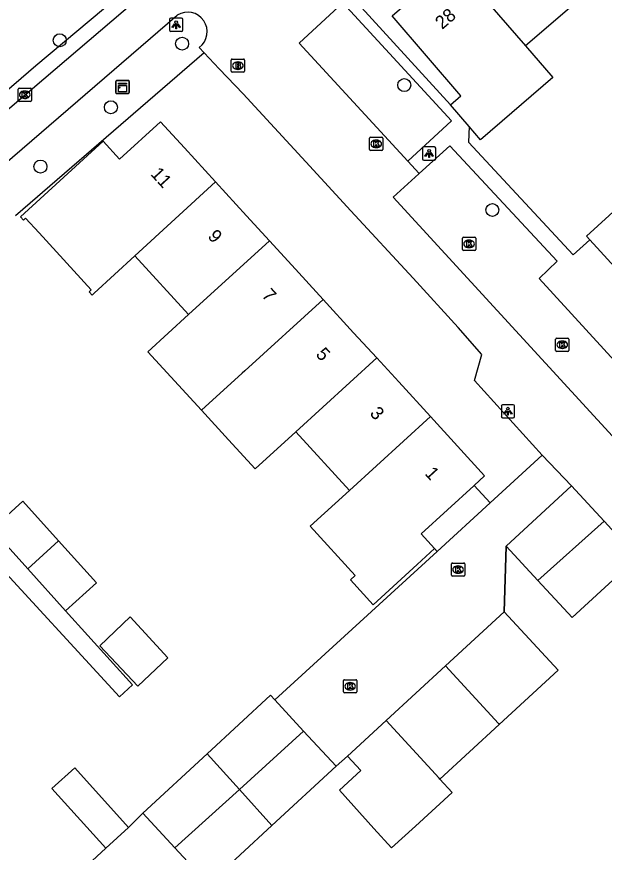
# Model space of a CAD drawing. Extents: x 158474 to 159560, y 388525 to 389605.
# Drawn here: x 159037.6 to 159082, y 388903.3 to 388966.4 of the extents above; entities that cross this region are included whole.
import ezdxf

# ---------------------------------------------------------------- set-up
doc = ezdxf.new("R2010")
doc.units = 0
for name, color, linetype in [('IMGEO_Boom', 7, 'Continuous'), ('IMGEO_Brandkraan', 7, 'Continuous'), ('IMGEO_Fietspad_gesloten', 7, 'Continuous'), ('IMGEO_Groenvoorziening', 7, 'Continuous'), ('IMGEO_Hek', 7, 'Continuous'), ('IMGEO_Kast', 7, 'Continuous'), ('IMGEO_Kolk', 7, 'Continuous'), ('IMGEO_Lichtpunt', 7, 'Continuous'), ('IMGEO_Muur', 7, 'Continuous'), ('IMGEO_Pand', 7, 'Continuous'), ('IMGEO_Pand_nummerreeks', 7, 'Continuous'), ('IMGEO_Rijbaan_lokaal_open', 7, 'Continuous'), ('IMGEO_Voetpad_open', 7, 'Continuous')]:
    doc.layers.add(name, color=color, linetype=linetype)

msp = doc.modelspace()

# ---------------------------------------------------------------- linework, layer by layer
at = {"layer": 'IMGEO_Boom'}
for centre in [(159040.871, 388964.606), (159050.107, 388964.349), (159066.882, 388961.222), (159044.73, 388959.546), (159039.41, 388955.073), (159073.534, 388951.792)]:
    msp.add_circle(centre, 0.489, dxfattribs=at)
at = {"layer": 'IMGEO_Brandkraan'}
for p, q in [((159053.896, 388963.19), (159054.748, 388963.19)), ((159053.821, 388962.264), (159053.821, 388963.116)), ((159054.309, 388962.97), (159054.334, 388962.97)), ((159054.822, 388963.116), (159054.822, 388962.264)), ((159054.748, 388962.19), (159053.896, 388962.19)), ((159054.332, 388962.41), (159054.307, 388962.41))]:
    msp.add_line(p, q, dxfattribs=at)
for points in [[(159053.896, 388963.19), (159054.748, 388963.19)], [(159053.821, 388962.264), (159053.821, 388963.116)], [(159054.169, 388962.89), (159054.169, 388962.49), (159054.382, 388962.49)], [(159054.4, 388962.89), (159054.169, 388962.89)], [(159054.348, 388962.809), (159054.294, 388962.809), (159054.294, 388962.733)], [(159054.294, 388962.733), (159054.347, 388962.733)], [(159054.356, 388962.657), (159054.294, 388962.657), (159054.294, 388962.576)], [(159054.294, 388962.576), (159054.356, 388962.576)], [(159054.822, 388963.116), (159054.822, 388962.264)], [(159054.748, 388962.19), (159053.896, 388962.19)]]:
    msp.add_lwpolyline(points, dxfattribs=at)
for centre, radius, start, end in [((159053.898, 388963.114), 0.0765, 91.55205, 178.44795), ((159053.898, 388963.114), 0.0765, 91.55205, 178.44795), ((159054.746, 388963.114), 0.0765, 1.55205, 88.44795), ((159054.746, 388963.114), 0.0765, 1.55205, 88.44795), ((159054.349, 388962.771), 0.0379, 267.82845, 90.93552), ((159054.357, 388962.616), 0.0404, 269.87594, 90.50774), ((159054.404, 388962.745), 0.145, 59.4692, 91.53667), ((159054.429, 388962.792), 0.0922, 285.51372, 58.15012), ((159054.434, 388962.6), 0.105, 301.31148, 78.98903), ((159053.898, 388962.266), 0.0765, 181.55205, 268.44795), ((159053.898, 388962.266), 0.0765, 181.55205, 268.44795), ((159054.388, 388962.741), 0.251, 268.66757, 293.53466), ((159054.746, 388962.266), 0.0765, 271.55205, 358.44795), ((159054.746, 388962.266), 0.0765, 271.55205, 358.44795)]:
    msp.add_arc(centre, radius, start, end, dxfattribs=at)
for centre, major_axis, ratio, start_param, end_param in [((159054.308, 388962.69), (-0.387, 0.002), 0.722429, 4.712389, 7.853982), ((159054.333, 388962.69), (-0.39, 0.002), 0.717154, 1.570796, 4.712389)]:
    msp.add_ellipse(centre, major_axis=major_axis, ratio=ratio, start_param=start_param, end_param=end_param, dxfattribs=at)
at = {"layer": 'IMGEO_Fietspad_gesloten'}
for points in [[(158982.556, 388907.1), (158984.126, 388908.89), (158991.035, 388916.747), (158993.803, 388919.761), (158997.258, 388923.376), (159000, 388926.236), (159000.439, 388926.694), (159004.156, 388930.365), (159007.355, 388933.494), (159010.208, 388936.145), (159013.072, 388938.778), (159015.935, 388941.39), (159018.694, 388943.743), (159033.647, 388956.597), (159049.939, 388970.49), (159054.573, 388974.475), (159070.579, 388988.241), (159084.209, 389000), (159114.372, 389026.022)], [(159035.257, 388954.041), (159049.743, 388966.513)]]:
    msp.add_lwpolyline(points, dxfattribs=at)
at = {"layer": 'IMGEO_Groenvoorziening'}
msp.add_lwpolyline([(159051.772, 388963.65), (159037.514, 388951.357)], dxfattribs=at)
at = {"layer": 'IMGEO_Hek'}
msp.add_lwpolyline([(159074.429, 388921.462), (159074.582, 388926.417)], dxfattribs=at)
at = {"layer": 'IMGEO_Kast'}
for p, q in [((159045.107, 388960.651), (159045.107, 388961.492)), ((159045.107, 388961.492), (159045.107, 388960.651)), ((159045.182, 388961.576), (159046.023, 388961.576)), ((159046.023, 388961.576), (159045.182, 388961.576)), ((159046.107, 388961.501), (159046.107, 388960.66)), ((159046.107, 388960.66), (159046.107, 388961.501)), ((159046.032, 388960.576), (159045.191, 388960.576)), ((159045.191, 388960.576), (159046.032, 388960.576))]:
    msp.add_line(p, q, dxfattribs=at)
for points in [[(159045.302, 388961.366), (159045.902, 388961.366), (159045.902, 388961.281), (159045.302, 388961.281), (159045.302, 388961.366)], [(159045.302, 388961.191), (159045.902, 388961.191), (159045.902, 388960.702), (159045.302, 388960.702), (159045.302, 388961.191)]]:
    msp.add_lwpolyline(points, dxfattribs=at)
msp.add_circle((159045.386, 388961.04), 0.0377, dxfattribs=at)
for centre, start, end in [((159045.185, 388961.498), 92.4484, 184.28452), ((159045.185, 388961.498), 92.4484, 184.28452), ((159046.029, 388961.498), 2.4484, 94.28452), ((159046.029, 388961.498), 2.4484, 94.28452), ((159045.185, 388960.654), 182.4484, 274.28452), ((159045.185, 388960.654), 182.4484, 274.28452), ((159046.029, 388960.654), 272.4484, 4.28452), ((159046.029, 388960.654), 272.4484, 4.28452)]:
    msp.add_arc(centre, 0.0779, start, end, dxfattribs=at)
at = {"layer": 'IMGEO_Kolk'}
for p, q in [((159037.721, 388960.066), (159037.721, 388960.918)), ((159037.796, 388960.992), (159038.648, 388960.992)), ((159038.209, 388960.772), (159038.234, 388960.772)), ((159038.722, 388960.918), (159038.722, 388960.066)), ((159038.232, 388960.212), (159038.207, 388960.212)), ((159038.648, 388959.992), (159037.796, 388959.992)), ((159064.263, 388956.358), (159064.263, 388957.21)), ((159064.338, 388957.284), (159065.19, 388957.284)), ((159064.751, 388957.064), (159064.776, 388957.064)), ((159065.264, 388957.21), (159065.264, 388956.358)), ((159065.19, 388956.284), (159064.338, 388956.284)), ((159064.774, 388956.504), (159064.749, 388956.504)), ((159071.276, 388948.807), (159071.276, 388949.659)), ((159071.351, 388949.733), (159072.203, 388949.733)), ((159071.764, 388949.513), (159071.789, 388949.513)), ((159072.277, 388949.659), (159072.277, 388948.807)), ((159072.203, 388948.733), (159071.351, 388948.733)), ((159071.787, 388948.953), (159071.762, 388948.953)), ((159078.314, 388941.192), (159078.314, 388942.044)), ((159078.389, 388942.118), (159079.241, 388942.118)), ((159078.802, 388941.898), (159078.827, 388941.898)), ((159079.315, 388942.044), (159079.315, 388941.192)), ((159079.241, 388941.118), (159078.389, 388941.118)), ((159078.825, 388941.338), (159078.8, 388941.338)), ((159070.447, 388924.213), (159070.447, 388925.065)), ((159070.522, 388925.139), (159071.374, 388925.139)), ((159070.935, 388924.919), (159070.96, 388924.919)), ((159071.448, 388925.065), (159071.448, 388924.213)), ((159071.374, 388924.139), (159070.522, 388924.139)), ((159070.958, 388924.359), (159070.933, 388924.359)), ((159062.295, 388915.404), (159062.295, 388916.256)), ((159062.37, 388916.33), (159063.222, 388916.33)), ((159062.783, 388916.11), (159062.808, 388916.11)), ((159063.296, 388916.256), (159063.296, 388915.404)), ((159063.222, 388915.33), (159062.37, 388915.33)), ((159062.806, 388915.55), (159062.781, 388915.55))]:
    msp.add_line(p, q, dxfattribs=at)
for points in [[(159037.721, 388960.066), (159037.721, 388960.918)], [(159037.796, 388960.992), (159038.648, 388960.992)], [(159038.042, 388960.692), (159038.165, 388960.692), (159038.165, 388960.541), (159038.295, 388960.692), (159038.459, 388960.692), (159038.313, 388960.541), (159038.466, 388960.292), (159038.314, 388960.292), (159038.229, 388960.456), (159038.165, 388960.389), (159038.165, 388960.292), (159038.042, 388960.292), (159038.042, 388960.692)], [(159038.722, 388960.918), (159038.722, 388960.066)], [(159038.648, 388959.992), (159037.796, 388959.992)], [(159064.263, 388956.358), (159064.263, 388957.21)], [(159064.338, 388957.284), (159065.19, 388957.284)], [(159064.584, 388956.984), (159064.707, 388956.984), (159064.707, 388956.833), (159064.837, 388956.984), (159065.001, 388956.984), (159064.855, 388956.833), (159065.008, 388956.584), (159064.856, 388956.584), (159064.771, 388956.748), (159064.707, 388956.681), (159064.707, 388956.584), (159064.584, 388956.584), (159064.584, 388956.984)], [(159065.264, 388957.21), (159065.264, 388956.358)], [(159065.19, 388956.284), (159064.338, 388956.284)], [(159071.276, 388948.807), (159071.276, 388949.659)], [(159071.351, 388949.733), (159072.203, 388949.733)], [(159071.597, 388949.433), (159071.72, 388949.433), (159071.72, 388949.282), (159071.85, 388949.433), (159072.014, 388949.433), (159071.868, 388949.282), (159072.021, 388949.033), (159071.869, 388949.033), (159071.784, 388949.197), (159071.72, 388949.13), (159071.72, 388949.033), (159071.597, 388949.033), (159071.597, 388949.433)], [(159072.277, 388949.659), (159072.277, 388948.807)], [(159072.203, 388948.733), (159071.351, 388948.733)], [(159078.314, 388941.192), (159078.314, 388942.044)], [(159078.389, 388942.118), (159079.241, 388942.118)], [(159078.635, 388941.818), (159078.758, 388941.818), (159078.758, 388941.667), (159078.888, 388941.818), (159079.052, 388941.818), (159078.906, 388941.667), (159079.059, 388941.418), (159078.907, 388941.418), (159078.822, 388941.582), (159078.758, 388941.515), (159078.758, 388941.418), (159078.635, 388941.418), (159078.635, 388941.818)], [(159079.315, 388942.044), (159079.315, 388941.192)], [(159079.241, 388941.118), (159078.389, 388941.118)], [(159070.447, 388924.213), (159070.447, 388925.065)], [(159070.522, 388925.139), (159071.374, 388925.139)], [(159070.768, 388924.839), (159070.891, 388924.839), (159070.891, 388924.688), (159071.021, 388924.839), (159071.185, 388924.839), (159071.039, 388924.688), (159071.192, 388924.439), (159071.04, 388924.439), (159070.955, 388924.603), (159070.891, 388924.536), (159070.891, 388924.439), (159070.768, 388924.439), (159070.768, 388924.839)], [(159071.448, 388925.065), (159071.448, 388924.213)], [(159071.374, 388924.139), (159070.522, 388924.139)], [(159062.295, 388915.404), (159062.295, 388916.256)], [(159062.37, 388916.33), (159063.222, 388916.33)], [(159062.616, 388916.03), (159062.739, 388916.03), (159062.739, 388915.879), (159062.869, 388916.03), (159063.033, 388916.03), (159062.887, 388915.879), (159063.04, 388915.63), (159062.888, 388915.63), (159062.803, 388915.794), (159062.739, 388915.727), (159062.739, 388915.63), (159062.616, 388915.63), (159062.616, 388916.03)], [(159063.296, 388916.256), (159063.296, 388915.404)], [(159063.222, 388915.33), (159062.37, 388915.33)]]:
    msp.add_lwpolyline(points, dxfattribs=at)
for centre, start, end in [((159037.798, 388960.916), 91.55205, 178.44795), ((159037.798, 388960.916), 91.55205, 178.44795), ((159038.646, 388960.916), 1.55205, 88.44795), ((159038.646, 388960.916), 1.55205, 88.44795), ((159037.798, 388960.068), 181.55205, 268.44795), ((159037.798, 388960.068), 181.55205, 268.44795), ((159038.646, 388960.068), 271.55205, 358.44795), ((159038.646, 388960.068), 271.55205, 358.44795), ((159064.34, 388957.208), 91.55205, 178.44795), ((159064.34, 388957.208), 91.55205, 178.44795), ((159065.188, 388957.208), 1.55205, 88.44795), ((159065.188, 388957.208), 1.55205, 88.44795), ((159064.34, 388956.36), 181.55205, 268.44795), ((159064.34, 388956.36), 181.55205, 268.44795), ((159065.188, 388956.36), 271.55205, 358.44795), ((159065.188, 388956.36), 271.55205, 358.44795), ((159071.353, 388949.657), 91.55205, 178.44795), ((159071.353, 388949.657), 91.55205, 178.44795), ((159072.201, 388949.657), 1.55205, 88.44795), ((159072.201, 388949.657), 1.55205, 88.44795), ((159071.353, 388948.809), 181.55205, 268.44795), ((159071.353, 388948.809), 181.55205, 268.44795), ((159072.201, 388948.809), 271.55205, 358.44795), ((159072.201, 388948.809), 271.55205, 358.44795), ((159078.391, 388942.042), 91.55205, 178.44795), ((159078.391, 388942.042), 91.55205, 178.44795), ((159079.239, 388942.042), 1.55205, 88.44795), ((159079.239, 388942.042), 1.55205, 88.44795), ((159078.391, 388941.194), 181.55205, 268.44795), ((159078.391, 388941.194), 181.55205, 268.44795), ((159079.239, 388941.194), 271.55205, 358.44795), ((159079.239, 388941.194), 271.55205, 358.44795), ((159070.524, 388925.063), 91.55205, 178.44795), ((159070.524, 388925.063), 91.55205, 178.44795), ((159071.372, 388925.063), 1.55205, 88.44795), ((159071.372, 388925.063), 1.55205, 88.44795), ((159070.524, 388924.215), 181.55205, 268.44795), ((159070.524, 388924.215), 181.55205, 268.44795), ((159071.372, 388924.215), 271.55205, 358.44795), ((159071.372, 388924.215), 271.55205, 358.44795), ((159062.372, 388916.254), 91.55205, 178.44795), ((159062.372, 388916.254), 91.55205, 178.44795), ((159063.22, 388916.254), 1.55205, 88.44795), ((159063.22, 388916.254), 1.55205, 88.44795), ((159062.372, 388915.406), 181.55205, 268.44795), ((159062.372, 388915.406), 181.55205, 268.44795), ((159063.22, 388915.406), 271.55205, 358.44795), ((159063.22, 388915.406), 271.55205, 358.44795)]:
    msp.add_arc(centre, 0.0765, start, end, dxfattribs=at)
for centre, major_axis, ratio, start_param, end_param in [((159038.208, 388960.492), (-0.387, 0.002), 0.722429, 4.712389, 7.853982), ((159038.233, 388960.492), (-0.39, 0.002), 0.717154, 1.570796, 4.712389), ((159064.75, 388956.784), (-0.387, 0.002), 0.722429, 4.712389, 7.853982), ((159064.775, 388956.784), (-0.39, 0.002), 0.717154, 1.570796, 4.712389), ((159071.763, 388949.233), (-0.387, 0.002), 0.722429, 4.712389, 7.853982), ((159071.788, 388949.233), (-0.39, 0.002), 0.717154, 1.570796, 4.712389), ((159078.801, 388941.618), (-0.387, 0.002), 0.722429, 4.712389, 7.853982), ((159078.826, 388941.618), (-0.39, 0.002), 0.717154, 1.570796, 4.712389), ((159070.934, 388924.639), (-0.387, 0.002), 0.722429, 4.712389, 7.853982), ((159070.959, 388924.639), (-0.39, 0.002), 0.717154, 1.570796, 4.712389), ((159062.782, 388915.83), (-0.387, 0.002), 0.722429, 4.712389, 7.853982), ((159062.807, 388915.83), (-0.39, 0.002), 0.717154, 1.570796, 4.712389)]:
    msp.add_ellipse(centre, major_axis=major_axis, ratio=ratio, start_param=start_param, end_param=end_param, dxfattribs=at)
at = {"layer": 'IMGEO_Lichtpunt'}
for p, q in [((159049.16, 388966.182), (159049.16, 388965.375)), ((159049.16, 388966.182), (159049.16, 388965.375)), ((159050.062, 388966.277), (159049.254, 388966.277)), ((159050.062, 388966.277), (159049.254, 388966.277)), ((159050.156, 388965.375), (159050.156, 388966.182)), ((159050.156, 388965.375), (159050.156, 388966.182)), ((159049.254, 388965.281), (159050.062, 388965.281)), ((159049.254, 388965.281), (159050.062, 388965.281)), ((159068.258, 388956.458), (159068.258, 388955.651)), ((159068.258, 388956.458), (159068.258, 388955.651)), ((159069.16, 388956.553), (159068.352, 388956.553)), ((159069.16, 388956.553), (159068.352, 388956.553)), ((159069.254, 388955.651), (159069.254, 388956.458)), ((159069.254, 388955.651), (159069.254, 388956.458)), ((159068.352, 388955.557), (159069.16, 388955.557)), ((159068.352, 388955.557), (159069.16, 388955.557)), ((159074.212, 388936.998), (159074.212, 388936.191)), ((159074.212, 388936.998), (159074.212, 388936.191)), ((159075.114, 388937.093), (159074.306, 388937.093)), ((159075.114, 388937.093), (159074.306, 388937.093)), ((159075.208, 388936.191), (159075.208, 388936.998)), ((159075.208, 388936.191), (159075.208, 388936.998)), ((159074.306, 388936.097), (159075.114, 388936.097)), ((159074.306, 388936.097), (159075.114, 388936.097))]:
    msp.add_line(p, q, dxfattribs=at)
for points in [[(159049.534, 388965.846), (159049.573, 388965.818), (159049.385, 388965.556), (159049.347, 388965.583), (159049.534, 388965.846)], [(159049.636, 388965.798), (159049.683, 388965.798), (159049.683, 388965.476), (159049.636, 388965.476), (159049.636, 388965.798)], [(159049.746, 388965.818), (159049.784, 388965.845), (159049.971, 388965.583), (159049.932, 388965.555), (159049.746, 388965.818)], [(159068.632, 388956.122), (159068.671, 388956.094), (159068.483, 388955.832), (159068.445, 388955.859), (159068.632, 388956.122)], [(159068.734, 388956.074), (159068.781, 388956.074), (159068.781, 388955.752), (159068.734, 388955.752), (159068.734, 388956.074)], [(159068.844, 388956.094), (159068.882, 388956.121), (159069.069, 388955.859), (159069.03, 388955.831), (159068.844, 388956.094)], [(159074.586, 388936.662), (159074.625, 388936.634), (159074.437, 388936.372), (159074.399, 388936.399), (159074.586, 388936.662)], [(159074.798, 388936.634), (159074.836, 388936.661), (159075.023, 388936.399), (159074.984, 388936.371), (159074.798, 388936.634)], [(159074.688, 388936.614), (159074.735, 388936.614), (159074.735, 388936.292), (159074.688, 388936.292), (159074.688, 388936.614)]]:
    msp.add_lwpolyline(points, dxfattribs=at)
for centre in [(159049.659, 388965.98), (159068.757, 388956.256), (159074.711, 388936.796)]:
    msp.add_circle(centre, 0.0994, dxfattribs=at)
for centre, start, end in [((159049.254, 388966.182), 90, 180), ((159049.254, 388966.182), 90, 180), ((159050.062, 388966.182), 0, 90), ((159050.062, 388966.182), 0, 90), ((159049.254, 388965.375), 180, 270), ((159049.254, 388965.375), 180, 270), ((159050.062, 388965.375), 270, 0), ((159050.062, 388965.375), 270, 360), ((159068.352, 388956.458), 90, 180), ((159068.352, 388956.458), 90, 180), ((159069.16, 388956.458), 0, 90), ((159069.16, 388956.458), 0, 90), ((159068.352, 388955.651), 180, 270), ((159068.352, 388955.651), 180, 270), ((159069.16, 388955.651), 270, 0), ((159069.16, 388955.651), 270, 360), ((159074.306, 388936.998), 90, 180), ((159074.306, 388936.998), 90, 180), ((159075.114, 388936.998), 0, 90), ((159075.114, 388936.998), 0, 90), ((159074.306, 388936.191), 180, 270), ((159074.306, 388936.191), 180, 270), ((159075.114, 388936.191), 270, 0), ((159075.114, 388936.191), 270, 360)]:
    msp.add_arc(centre, 0.0946, start, end, dxfattribs=at)
at = {"layer": 'IMGEO_Muur'}
msp.add_lwpolyline([(159071.795, 388958.09), (159071.74, 388956.903), (159079.631, 388948.405)], dxfattribs=at)
at = {"layer": 'IMGEO_Pand'}
for points in [[(159070.383, 388959.731), (159071.162, 388960.402), (159065.957, 388966.45), (159070.61, 388970.456)], [(159070.61, 388970.456), (159076.04, 388964.187)], [(159079.662, 388969.176), (159080.585, 388968.1), (159076.04, 388964.187)], [(159076.04, 388964.187), (159078.1, 388961.795), (159072.647, 388957.1), (159071.795, 388958.09)], [(159071.795, 388958.09), (159070.383, 388959.731)], [(159046.534, 388948.322), (159043.474, 388945.52), (159043.304, 388945.365), (159043.081, 388945.609), (159043.251, 388945.764), (159039.312, 388950.065), (159038.292, 388951.179), (159038.123, 388951.023), (159037.9, 388951.267), (159044.149, 388956.989), (159045.391, 388955.632), (159048.474, 388958.455), (159050.28, 388956.482), (159052.637, 388953.909)], [(159052.637, 388953.909), (159046.534, 388948.322)], [(159052.637, 388953.909), (159054.98, 388951.351), (159056.697, 388949.475)], [(159080.886, 388949.549), (159080.65, 388949.807), (159085.506, 388954.236), (159087.885, 388951.628)], [(159056.697, 388949.475), (159050.592, 388943.89)], [(159056.697, 388949.475), (159058.38, 388947.638), (159060.754, 388945.045)], [(159083.034, 388947.194), (159080.886, 388949.549)], [(159050.592, 388943.89), (159046.534, 388948.322)], [(159060.754, 388945.045), (159054.841, 388939.653), (159054.641, 388939.47), (159051.575, 388936.674)], [(159060.754, 388945.045), (159063.058, 388942.529), (159064.805, 388940.621)], [(159051.575, 388936.674), (159047.531, 388941.09), (159050.592, 388943.89)], [(159058.689, 388935.049), (159064.805, 388940.621)], [(159064.805, 388940.621), (159066.462, 388938.812), (159068.864, 388936.188)], [(159058.689, 388935.049), (159055.629, 388932.247), (159053.618, 388934.443), (159051.575, 388936.674)], [(159068.864, 388936.188), (159062.747, 388930.618)], [(159068.864, 388936.188), (159072.95, 388931.727), (159072.153, 388930.997)], [(159062.747, 388930.618), (159058.689, 388935.049)], [(159072.153, 388930.997), (159072.125, 388930.971), (159068.149, 388927.33), (159069.163, 388926.223)], [(159072.153, 388930.997), (159073.36, 388929.677)], [(159069.163, 388926.223), (159067.862, 388925.032), (159064.543, 388921.993), (159062.821, 388923.873), (159063.187, 388924.192), (159059.789, 388927.924), (159062.747, 388930.618)], [(159074.582, 388926.417), (159079.511, 388930.955)], [(159079.511, 388930.955), (159081.967, 388928.286)], [(159040.774, 388926.824), (159038.082, 388929.805), (159035.749, 388927.698)], [(159069.354, 388926.014), (159073.36, 388929.677)], [(159076.965, 388923.829), (159081.967, 388928.286)], [(159081.967, 388928.286), (159084.485, 388925.551)], [(159038.451, 388924.705), (159035.749, 388927.698)], [(159040.774, 388926.824), (159038.451, 388924.705)], [(159041.308, 388921.54), (159043.642, 388923.647), (159040.774, 388926.824)], [(159069.354, 388926.014), (159069.163, 388926.223)], [(159076.965, 388923.829), (159074.582, 388926.417)], [(159084.485, 388925.551), (159079.556, 388921.014), (159076.965, 388923.829)], [(159041.308, 388921.54), (159038.451, 388924.705)], [(159046.184, 388921.073), (159043.883, 388918.896), (159046.772, 388915.844), (159049.023, 388917.976), (159046.184, 388921.073)], [(159069.992, 388917.372), (159074.429, 388921.462)], [(159074.429, 388921.462), (159078.495, 388917.051), (159074.044, 388912.948)], [(159065.512, 388913.243), (159069.992, 388917.372)], [(159069.992, 388917.372), (159073.99, 388913.02), (159074.044, 388912.948)], [(159051.996, 388910.732), (159056.776, 388915.153), (159057.097, 388914.806)], [(159057.097, 388914.806), (159059.274, 388912.453)], [(159065.512, 388913.243), (159062.593, 388910.552)], [(159069.568, 388908.823), (159069.51, 388908.9), (159065.512, 388913.243)], [(159074.044, 388912.948), (159069.568, 388908.823)], [(159054.43, 388908.05), (159059.274, 388912.453)], [(159059.274, 388912.453), (159061.734, 388909.793)], [(159047.144, 388906.244), (159051.996, 388910.732)], [(159051.996, 388910.732), (159054.43, 388908.05)], [(159062.593, 388910.552), (159063.59, 388909.47), (159061.985, 388907.991), (159064.591, 388905.105), (159065.927, 388903.625), (159067.728, 388905.28), (159070.489, 388907.822), (159069.568, 388908.823)], [(159044.34, 388903.612), (159040.28, 388908.103), (159042.012, 388909.668), (159046.071, 388905.177)], [(159061.734, 388909.793), (159056.892, 388905.314)], [(159049.561, 388903.63), (159054.43, 388908.05)], [(159054.43, 388908.05), (159056.88, 388905.33), (159056.892, 388905.314)], [(159047.144, 388906.244), (159049.561, 388903.63)], [(159044.34, 388903.612), (159046.071, 388905.177)], [(159056.892, 388905.314), (159052.102, 388900.883)], [(159049.561, 388903.63), (159052.102, 388900.883)]]:
    msp.add_lwpolyline(points, dxfattribs=at)
at = {"layer": 'IMGEO_Rijbaan_lokaal_open'}
for points in [[(159068.016, 388954.544), (159070.323, 388956.636), (159078.421, 388947.93), (159077.068, 388946.614), (159092.522, 388929.727)], [(159089.944, 388926.697), (159083.426, 388933.811), (159066.034, 388952.748), (159067.989, 388954.52), (159068.016, 388954.544)], [(159073.36, 388929.677), (159077.292, 388933.272)], [(159077.292, 388933.272), (159079.511, 388930.955)], [(159057.097, 388914.806), (159069.354, 388926.014)], [(159074.582, 388926.417), (159074.429, 388921.462)], [(159062.593, 388910.552), (159061.734, 388909.793)], [(159046.071, 388905.177), (159047.144, 388906.244)], [(159038.924, 388898.606), (159044.34, 388903.612)]]:
    msp.add_lwpolyline(points, dxfattribs=at)
at = {"layer": 'IMGEO_Voetpad_open'}
for points in [[(159053.465, 388974.766), (159039.062, 388962.688), (159030.194, 388955.059)], [(159070.383, 388959.731), (159062.836, 388967.979)], [(159067.162, 388955.486), (159058.942, 388964.389), (159062.236, 388967.43)], [(159062.236, 388967.43), (159070.455, 388958.526), (159067.162, 388955.486)], [(159051.407, 388964.07), (159051.772, 388963.65)], [(159077.292, 388933.272), (159072.177, 388938.914), (159072.727, 388940.876), (159070.954, 388942.926), (159067.55, 388946.643), (159062.838, 388951.72), (159059.438, 388955.433), (159054.726, 388960.554), (159052.916, 388962.443), (159051.772, 388963.65)], [(159071.795, 388958.09), (159071.74, 388956.903), (159079.631, 388948.405), (159080.886, 388949.549)], [(159067.162, 388955.486), (159068.016, 388954.544)], [(159035.368, 388925.912), (159045.37, 388915.032), (159046.359, 388915.941), (159041.308, 388921.54)]]:
    msp.add_lwpolyline(points, dxfattribs=at)
msp.add_arc((159050.516, 388965.251), 1.48, 307.02918, 121.4907, dxfattribs=at)

# ---------------------------------------------------------------- texts
at = {"layer": 'IMGEO_Pand_nummerreeks'}
for s, rotation, p in [('28', 40.72196, (159069.746, 388965.384)), ('11', 312.4817, (159047.675, 388954.471)), ('9', 312.4817, (159051.988, 388949.761)), ('7', 312.47888, (159056.068, 388945.306)), ('5', 312.47888, (159060.147, 388940.851)), ('3', 312.4817, (159064.226, 388936.397)), ('1', 312.47888, (159068.383, 388931.858))]:
    msp.add_text(s, height=1, rotation=rotation, dxfattribs=at).set_placement(p)

doc.saveas('drawing.dxf')
